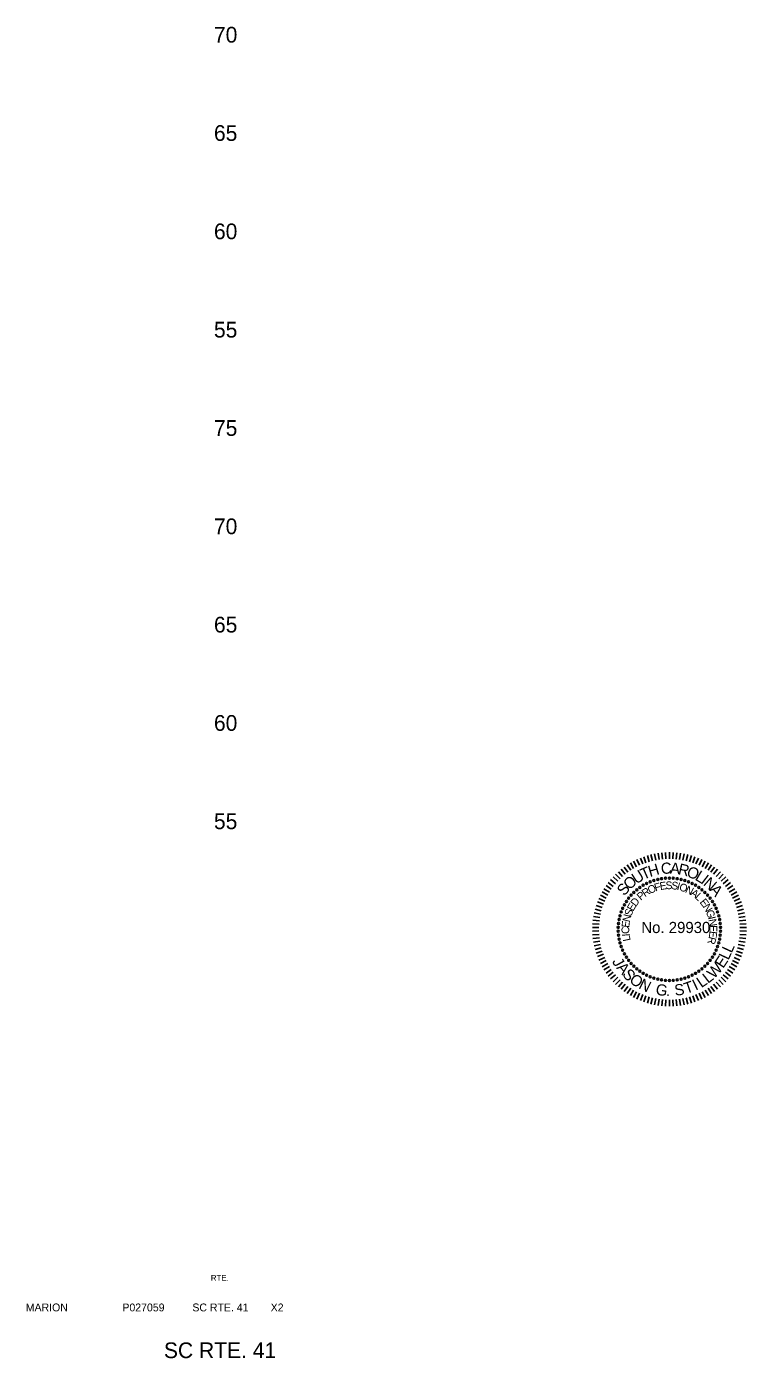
# Model space of a CAD drawing. Extents: x 952 to 1206, y 942 to 2399.
# Drawn here: x 1147.4 to 1184, y 1788.1 to 1855.8 of the extents above; entities that cross this region are included whole.
import ezdxf

# ---------------------------------------------------------------- set-up
doc = ezdxf.new("R2010")
doc.units = 0
for name, color, linetype in [('Default', 7, 'Continuous'), ('RD_SHT_TX', 7, 'Continuous'), ('RD_TX_PEShield', 7, 'Continuous'), ('RD_XS_TX_Elev_EX', 7, 'Continuous')]:
    doc.layers.add(name, color=color, linetype=linetype)

# ---------------------------------------------------------------- blocks, each defined once
blk = doc.blocks.new('STILLWELL')
at = {"layer": 'RD_TX_PEShield'}
for p, q in [((-15.14, 31.6), (-16.52, 34.56)), ((-13.55, 32.29), (-14.79, 35.32)), ((-11.93, 32.91), (-13.02, 35.99)), ((-10.28, 33.44), (-11.22, 36.57)), ((-8.61, 33.9), (-9.39, 37.07)), ((-6.92, 34.27), (-7.55, 37.48)), ((-5.21, 34.57), (-5.68, 37.8)), ((-3.49, 34.77), (-3.81, 38.03)), ((-1.76, 34.9), (-1.92, 38.16)), ((-0.03, 34.94), (-0.03, 38.21)), ((1.71, 34.9), (1.86, 38.16)), ((3.43, 34.77), (3.75, 38.03)), ((5.15, 34.57), (5.63, 37.8)), ((6.86, 34.27), (7.49, 37.48)), ((8.56, 33.9), (9.34, 37.07)), ((10.23, 33.44), (11.16, 36.57)), ((11.88, 32.91), (12.96, 35.99)), ((13.5, 32.29), (14.73, 35.32)), ((15.09, 31.6), (16.46, 34.56)), ((-23.81, 25.92), (-25.98, 28.37)), ((-22.49, 27.04), (-24.53, 29.59)), ((-21.11, 28.09), (-23.03, 30.73)), ((-19.68, 29.08), (-21.48, 31.81)), ((-18.21, 29.99), (-19.87, 32.81)), ((-16.7, 30.83), (-18.22, 33.73)), ((16.64, 30.83), (18.16, 33.73)), ((18.16, 29.99), (19.81, 32.81)), ((19.63, 29.08), (21.42, 31.81)), ((21.06, 28.09), (22.98, 30.73)), ((22.43, 27.04), (24.48, 29.59)), ((23.76, 25.92), (25.92, 28.37)), ((-29.55, 19.45), (-32.24, 21.3)), ((-28.53, 20.85), (-31.12, 22.83)), ((-27.44, 22.2), (-29.94, 24.31)), ((-26.29, 23.5), (-28.69, 25.72)), ((-25.08, 24.74), (-27.37, 27.08)), ((25.03, 24.74), (27.31, 27.08)), ((26.24, 23.5), (28.63, 25.72)), ((27.39, 22.2), (29.88, 24.31)), ((28.47, 20.85), (31.07, 22.83)), ((29.49, 19.45), (32.18, 21.3)), ((-32.91, 13.4), (-35.91, 14.7)), ((-32.18, 14.97), (-35.11, 16.42)), ((-31.38, 16.5), (-34.23, 18.09)), ((-30.5, 18), (-33.27, 19.72)), ((30.44, 18), (33.22, 19.72)), ((31.32, 16.5), (34.18, 18.09)), ((32.13, 14.97), (35.06, 16.42)), ((32.86, 13.4), (35.85, 14.7)), ((-35.05, 6.81), (-38.24, 7.52)), ((-34.64, 8.5), (-37.79, 9.35)), ((-34.14, 10.16), (-37.25, 11.17)), ((-33.57, 11.79), (-36.62, 12.95)), ((33.51, 11.79), (36.57, 12.95)), ((34.09, 10.16), (37.19, 11.17)), ((34.58, 8.5), (37.73, 9.35)), ((35, 6.81), (38.19, 7.52)), ((-35.89, -0.06), (-39.15, 0.02)), ((-35.8, 1.67), (-39.06, 1.91)), ((-35.64, 3.4), (-38.88, 3.79)), ((-35.39, 5.11), (-38.61, 5.66)), ((35.33, 5.11), (38.55, 5.66)), ((35.58, 3.4), (38.82, 3.79)), ((35.75, 1.67), (39.01, 1.91)), ((35.83, -0.06), (39.1, 0.02)), ((-35.89, -1.79), (-39.15, -1.87)), ((-35.8, -3.53), (-39.06, -3.76)), ((-35.64, -5.25), (-38.88, -5.65)), ((35.58, -5.25), (38.82, -5.65)), ((35.75, -3.53), (39.01, -3.76)), ((35.83, -1.79), (39.1, -1.87)), ((-35.39, -6.97), (-38.61, -7.52)), ((-35.05, -8.67), (-38.24, -9.37)), ((-34.64, -10.35), (-37.79, -11.21)), ((-34.14, -12.01), (-37.25, -13.02)), ((34.09, -12.01), (37.19, -13.02)), ((34.58, -10.35), (37.73, -11.21)), ((35, -8.67), (38.19, -9.37)), ((35.33, -6.97), (38.55, -7.52)), ((-33.57, -13.65), (-36.62, -14.81)), ((-32.91, -15.25), (-35.91, -16.56)), ((-32.18, -16.83), (-35.11, -18.27)), ((-31.38, -18.36), (-34.23, -19.95)), ((-30.5, -19.85), (-33.27, -21.58)), ((30.44, -19.85), (33.22, -21.58)), ((31.32, -18.36), (34.18, -19.95)), ((32.13, -16.83), (35.06, -18.27)), ((32.86, -15.25), (35.85, -16.56)), ((33.51, -13.65), (36.57, -14.81)), ((-29.55, -21.3), (-32.24, -23.16)), ((-28.53, -22.71), (-31.12, -24.69)), ((-27.44, -24.06), (-29.94, -26.16)), ((-26.29, -25.36), (-28.69, -27.58)), ((-25.08, -26.6), (-27.37, -28.93)), ((25.03, -26.6), (27.31, -28.93)), ((26.24, -25.36), (28.63, -27.58)), ((27.39, -24.06), (29.88, -26.16)), ((28.47, -22.71), (31.07, -24.69)), ((29.49, -21.3), (32.18, -23.16)), ((-23.81, -27.78), (-25.98, -30.22)), ((-22.49, -28.89), (-24.53, -31.44)), ((-21.11, -29.95), (-23.03, -32.59)), ((-19.68, -30.93), (-21.48, -33.66)), ((-18.21, -31.85), (-19.87, -34.66)), ((-16.7, -32.69), (-18.22, -35.58)), ((-15.14, -33.46), (-16.52, -36.42)), ((15.09, -33.46), (16.46, -36.42)), ((16.64, -32.69), (18.16, -35.58)), ((18.16, -31.85), (19.81, -34.66)), ((19.63, -30.93), (21.42, -33.66)), ((21.06, -29.95), (22.98, -32.59)), ((22.43, -28.89), (24.48, -31.44)), ((23.76, -27.78), (25.92, -30.22)), ((-13.55, -34.15), (-14.79, -37.18)), ((-11.93, -34.76), (-13.02, -37.85)), ((-10.28, -35.3), (-11.22, -38.43)), ((-8.61, -35.76), (-9.39, -38.93)), ((-6.92, -36.13), (-7.55, -39.34)), ((-5.21, -36.42), (-5.68, -39.65)), ((-3.49, -36.63), (-3.81, -39.88)), ((-1.76, -36.76), (-1.92, -40.02)), ((-0.03, -36.8), (-0.03, -40.06)), ((1.71, -36.76), (1.86, -40.02)), ((3.43, -36.63), (3.75, -39.88)), ((5.15, -36.42), (5.63, -39.65)), ((6.86, -36.13), (7.49, -39.34)), ((8.56, -35.76), (9.34, -38.93)), ((10.23, -35.3), (11.16, -38.43)), ((11.88, -34.76), (12.96, -37.85)), ((13.5, -34.15), (14.73, -37.18))]:
    blk.add_line(p, q, dxfattribs=at)
for centre in [(-15.01, 20.38), (-13.34, 21.46), (-11.59, 22.41), (-9.76, 23.23), (-7.89, 23.9), (-5.96, 24.43), (-4, 24.81), (-2.02, 25.04), (-0.03, 25.12), (1.97, 25.04), (3.95, 24.81), (5.91, 24.43), (7.83, 23.9), (9.71, 23.23), (11.53, 22.41), (13.28, 21.46), (14.96, 20.38), (-21.89, 13.23), (-20.74, 14.86), (-19.47, 16.4), (-18.09, 17.84), (-16.6, 19.17), (16.54, 19.17), (18.03, 17.84), (19.42, 16.4), (20.69, 14.86), (21.83, 13.23), (-24.54, 7.88), (-23.79, 9.73), (-22.91, 11.51), (22.85, 11.51), (23.74, 9.73), (24.48, 7.88), (-26.05, 0.07), (-25.9, 2.06), (-25.6, 4.03), (-25.14, 5.97), (25.09, 5.97), (25.54, 4.03), (25.85, 2.06), (26, 0.07), (-26.05, -1.93), (-25.9, -3.92), (-25.6, -5.89), (25.54, -5.89), (25.85, -3.92), (26, -1.93), (-25.14, -7.83), (-24.54, -9.73), (-23.79, -11.58), (-22.91, -13.37), (22.85, -13.37), (23.74, -11.58), (24.48, -9.73), (25.09, -7.83), (-21.89, -15.09), (-20.74, -16.72), (-19.47, -18.26), (-18.09, -19.69), (18.03, -19.69), (19.42, -18.26), (20.69, -16.72), (21.83, -15.09), (-16.6, -21.02), (-15.01, -22.23), (-13.34, -23.32), (-11.59, -24.27), (-9.76, -25.09), (-7.89, -25.76), (-5.96, -26.29), (-4, -26.67), (-2.02, -26.9), (-0.03, -26.97), (1.97, -26.9), (3.95, -26.67), (5.91, -26.29), (7.83, -25.76), (9.71, -25.09), (11.53, -24.27), (13.28, -23.32), (14.96, -22.23), (16.54, -21.02)]:
    blk.add_circle(centre, 0.49, dxfattribs=at)
for s, height, rotation, p in [('U', 5.68, 32.21524, (-16.89, 21.85)), ('T', 5.68, 23.50438, (-13.24, 24.14)), ('H', 5.68, 16.13567, (-9.92, 25.63)), ('C', 5.68, 4.07599, (-4.15, 27.11)), ('A', 5.68, 355.36513, (0.14, 27.41)), ('R', 5.68, 347.31877, (4.1, 27.11)), ('O', 5.68, 338.6079, (8.3, 26.16)), ('L', 5.68, 329.22596, (12.61, 24.44)), ('S', 5.68, 49.64355, (-22.94, 15.75)), ('O', 5.68, 41.59718, (-20.38, 18.79)), ('O', 3.92, 24.97351, (-9.98, 16.95)), ('F', 3.92, 15.99945, (-7.07, 18.28)), ('E', 3.92, 8.95111, (-4.65, 19)), ('S', 3.92, 1.25456, (-1.94, 19.44)), ('S', 3.92, 353.55802, (0.8, 19.51)), ('I', 3.92, 345.86148, (3.53, 19.22)), ('O', 3.92, 342.65826, (4.65, 18.99)), ('N', 3.92, 333.6842, (7.7, 18.01)), ('I', 5.68, 322.52176, (15.48, 22.79)), ('N', 5.68, 319.17294, (16.84, 21.84)), ('A', 5.68, 310.46208, (20.09, 19.02)), ('D', 3.92, 52.53758, (-17.12, 10.32)), ('P', 3.92, 41.0022, (-14.52, 13.51)), ('R', 3.92, 33.30566, (-12.46, 15.32)), ('A', 3.92, 325.35205, (10.36, 16.69)), ('L', 3.92, 317.65551, (12.63, 15.14)), ('E', 3.92, 308.03955, (15.14, 12.8)), ('S', 3.92, 67.93066, (-19.49, 5.38)), ('E', 3.92, 60.23412, (-18.47, 7.93)), ('N', 3.92, 300.34301, (16.84, 10.65)), ('G', 3.92, 292.01086, (18.34, 8.08)), ('C', 3.92, 92.29151, (-20.36, -3.21)), ('E', 3.92, 83.95936, (-20.47, -0.24)), ('N', 3.92, 76.26281, (-20.2, 2.49)), ('I', 3.92, 283.0368, (19.52, 5.11)), ('N', 3.92, 279.83358, (19.83, 4.01)), ('E', 3.92, 271.50143, (20.33, 1.08)), ('I', 3.92, 95.49473, (-20.2, -4.35)), ('L', 3.92, 101.90747, (-19.69, -6.58)), ('R', 3.92, 256.10834, (20.13, -4.4)), ('E', 3.92, 263.80489, (20.42, -1.67)), ('L', 5.68, 65.09801, (29.98, -16.89)), ('L', 5.68, 65.09801, (31.58, -13.34)), ('J', 5.68, 299.03302, (-29.35, -17.26)), ('A', 5.68, 310.58873, (-27.19, -20.61)), ('W', 5.68, 47.05177, (22.62, -26.41)), ('E', 5.68, 56.4327, (27.3, -21.12)), ('S', 5.68, 310.58873, (-24.3, -23.99)), ('O', 5.68, 321.00719, (-20.82, -27.39)), ('N', 5.68, 333.43256, (-16.05, -30.75)), ('T', 5.68, 18.90189, (8.5, -33.88)), ('I', 5.68, 25.39911, (13.3, -32.17)), ('L', 5.68, 34.06442, (16.21, -30.92)), ('L', 5.68, 37.67084, (19.57, -28.72)), ('G', 5.68, 352.2045, (-7.22, -34.2)), ('S', 5.68, 8.08265, (2.93, -34.79)), ('.', 5.68, 0.86982, (-1.8, -34.9))]:
    blk.add_text(s, height=height, rotation=rotation, dxfattribs=at).set_placement(p)
blk.add_text('No. 29930', height=5.685, dxfattribs=at).set_placement((-14.3, -2.84))

msp = doc.modelspace()

# ---------------------------------------------------------------- block references
at = {"layer": 'Default', "xscale": 0.1, "yscale": 0.10000000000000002}
msp.add_blockref('STILLWELL', (1180.075, 1810), dxfattribs=at)

# ---------------------------------------------------------------- texts
at = {"layer": 'RD_SHT_TX'}
for s, height, p in [('RTE.', 0.3, (1156.759, 1792.03)), ('MARION', 0.4, (1147.353, 1790.476)), ('P027059', 0.4, (1152.265, 1790.476)), ('SC RTE. 41', 0.4, (1155.822, 1790.476)), ('X2', 0.4, (1159.803, 1790.476)), ('SC RTE. 41', 0.8, (1154.376, 1788.098))]:
    msp.add_text(s, height=height, dxfattribs=at).set_placement(p)
at = {"layer": 'RD_XS_TX_Elev_EX'}
for s, p in [('70', (1156.919, 1855)), ('65', (1156.919, 1850)), ('60', (1156.919, 1845)), ('55', (1156.919, 1840)), ('75', (1156.919, 1835)), ('70', (1156.919, 1830)), ('65', (1156.919, 1825)), ('60', (1156.919, 1820)), ('55', (1156.919, 1815))]:
    msp.add_text(s, height=0.8, dxfattribs=at).set_placement(p)

doc.saveas('drawing.dxf')
